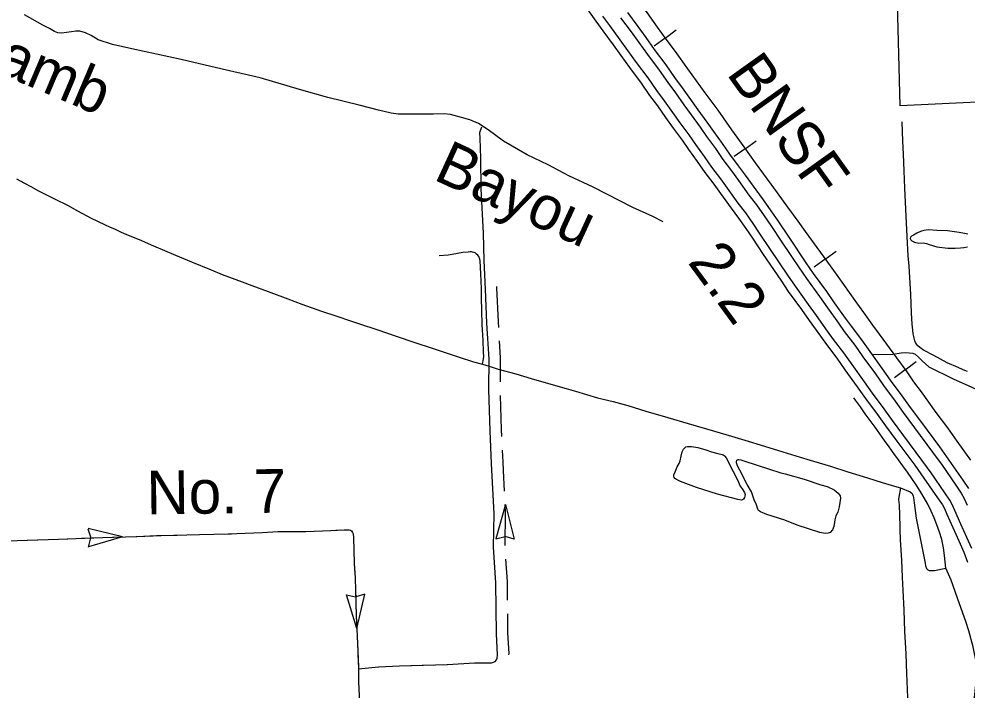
# Model space of a CAD drawing. Extents: x -117616 to 64730, y 54117 to 789866.
# Drawn here: x 62704.7 to 62888.1, y 54864.5 to 54994.3 of the extents above; entities that cross this region are included whole.
import ezdxf

# ---------------------------------------------------------------- set-up
doc = ezdxf.new("R2010")
doc.units = 0
for name, color, linetype in [('15', 7, 'Continuous'), ('27', 7, 'Continuous'), ('33', 7, 'Continuous'), ('34', 7, 'Continuous'), ('35', 7, 'Continuous'), ('40', 7, 'Continuous'), ('43', 7, 'Continuous'), ('48', 7, 'Continuous'), ('6', 7, 'Continuous')]:
    doc.layers.add(name, color=color, linetype=linetype)

msp = doc.modelspace()

# ---------------------------------------------------------------- linework, layer by layer
at = {"layer": '15'}
for points in [[(62814.33, 54996.58), (62816.27, 54993.87), (62817.59, 54992.01), (62819.63, 54989.27), (62821.11, 54987.23), (62822.76, 54984.88), (62825.02, 54981.9), (62826.68, 54979.48), (62828.18, 54977.48), (62829.77, 54975.21), (62831.22, 54973.21), (62832.94, 54970.87), (62834.21, 54969.05), (62835.89, 54966.73), (62837.36, 54964.61), (62839.07, 54962.35), (62840.36, 54960.55), (62842.45, 54957.68), (62843.88, 54955.8), (62845.28, 54953.78), (62846.55, 54951.92), (62848.67, 54948.76), (62852.03, 54943.77), (62853.51, 54941.61), (62856.06, 54938.11), (62857.57, 54935.96), (62859.71, 54932.95), (62860.88, 54931.32), (62862.87, 54928.69), (62864.45, 54926.46), (62866.85, 54923.16), (62868.43, 54920.91), (62870.68, 54917.87), (62872.28, 54915.64), (62874.49, 54912.66), (62877.96, 54907.99), (62879.75, 54905.52), (62882.38, 54901.69), (62883.32, 54900.33), (62883.7, 54899.65), (62884.19, 54898.53), (62885.35, 54895.93), (62886.49, 54893.35), (62887.46, 54891.21), (62888.2, 54889.23)], [(62888.43, 54903.49), (62887.32, 54905.09), (62884.66, 54908.98), (62882.8, 54911.54), (62879.31, 54916.23), (62877.13, 54919.17), (62875.53, 54921.41), (62873.3, 54924.42), (62871.73, 54926.65), (62869.32, 54929.96), (62867.72, 54932.23), (62865.71, 54934.88), (62864.59, 54936.44), (62862.47, 54939.42), (62860.94, 54941.6), (62858.41, 54945.08), (62856.99, 54947.14), (62853.65, 54952.11), (62851.52, 54955.28), (62850.22, 54957.18), (62848.73, 54959.33), (62847.26, 54961.26), (62845.23, 54964.06), (62843.9, 54965.91), (62842.22, 54968.13), (62840.78, 54970.2), (62839.1, 54972.53), (62837.82, 54974.36), (62836.07, 54976.75), (62834.66, 54978.69), (62833.04, 54981.01), (62831.56, 54982.98), (62829.89, 54985.41), (62827.61, 54988.42), (62825.99, 54990.72), (62824.46, 54992.82), (62822.44, 54995.54)], [(62889.03, 54891.86), (62888.05, 54894.05), (62886.91, 54896.62), (62885.75, 54899.22), (62885.22, 54900.41), (62884.77, 54901.22), (62883.78, 54902.65), (62881.14, 54906.5), (62879.33, 54909), (62875.85, 54913.67), (62873.66, 54916.64), (62872.05, 54918.88), (62869.81, 54921.91), (62868.23, 54924.15), (62865.83, 54927.45), (62864.25, 54929.7), (62862.25, 54932.33), (62861.09, 54933.94), (62858.96, 54936.94), (62857.44, 54939.1), (62854.9, 54942.6), (62853.43, 54944.72), (62850.08, 54949.71), (62847.96, 54952.87), (62846.68, 54954.75), (62845.26, 54956.8), (62843.81, 54958.69), (62841.74, 54961.55), (62840.44, 54963.36), (62838.74, 54965.61), (62837.27, 54967.72), (62835.59, 54970.04), (62834.32, 54971.86), (62832.59, 54974.21), (62831.15, 54976.2), (62829.56, 54978.48), (62828.06, 54980.47), (62826.4, 54982.9), (62824.14, 54985.88), (62822.49, 54988.22), (62821, 54990.27), (62818.97, 54993.01), (62817.65, 54994.86)], [(62821.07, 54994.54), (62823.09, 54991.81), (62824.61, 54989.73), (62826.24, 54987.42), (62828.51, 54984.42), (62830.18, 54981.98), (62831.66, 54980.01), (62833.27, 54977.71), (62834.69, 54975.75), (62836.44, 54973.37), (62837.71, 54971.54), (62839.4, 54969.22), (62840.84, 54967.13), (62842.53, 54964.9), (62843.85, 54963.07), (62845.9, 54960.25), (62847.36, 54958.33), (62848.82, 54956.22), (62850.11, 54954.33), (62852.24, 54951.16), (62855.58, 54946.19), (62857.02, 54944.1), (62859.56, 54940.61), (62861.08, 54938.44), (62863.21, 54935.45), (62864.34, 54933.87), (62866.35, 54931.23), (62867.94, 54928.97), (62870.35, 54925.66), (62871.92, 54923.43), (62874.15, 54920.41), (62875.76, 54918.17), (62877.94, 54915.22), (62881.43, 54910.54), (62883.27, 54908), (62885.92, 54904.13), (62886.98, 54902.59), (62887.55, 54901.56), (62888.12, 54900.28)]]:
    msp.add_lwpolyline(points, dxfattribs=at)
at = {"layer": '27'}
for points in [[(62883.96, 54888.07), (62883.74, 54890.52), (62883.51, 54892.03), (62883.19, 54893.65), (62882.73, 54895.06), (62882.24, 54896.45), (62881.71, 54897.81), (62881.12, 54899.14), (62880.47, 54900.45), (62879.77, 54901.72), (62879.03, 54902.98), (62878.24, 54904.22), (62877.41, 54905.44), (62876.54, 54906.64), (62875.68, 54907.85), (62874.8, 54909.07), (62873.92, 54910.29), (62873.03, 54911.53), (62872.12, 54912.79), (62871.2, 54914.06), (62870.28, 54915.34), (62869.34, 54916.63), (62868.4, 54917.94), (62867.46, 54919.26), (62866.5, 54920.58), (62866.18, 54921.03)], [(62890.36, 54854.84), (62889.64, 54857.65), (62889.48, 54859.72), (62889.37, 54861.95), (62889.58, 54863.65), (62889.79, 54865.56), (62890.01, 54867.58), (62890.01, 54869.38), (62889.26, 54872.89), (62888.41, 54875.97), (62887.88, 54877.78), (62886.61, 54881.17), (62885.02, 54885.74), (62883.96, 54888.07)]]:
    msp.add_lwpolyline(points, dxfattribs=at)
at = {"layer": '33'}
for points in [[(62704.16, 54963.36), (62705.73, 54962.54), (62706.98, 54961.89), (62708.44, 54961.07), (62711.65, 54959.45), (62714.02, 54958.27), (62716, 54957.22), (62718.65, 54955.79), (62721.2, 54954.55), (62722.28, 54954.05), (62723.17, 54953.69), (62724.45, 54953.05), (62725.76, 54952.5), (62727.9, 54951.63), (62730.67, 54950.45), (62734.96, 54948.64), (62738.06, 54947.33), (62741.86, 54945.79), (62743.99, 54944.91), (62747.87, 54943.47), (62749.74, 54942.73), (62752.89, 54941.56), (62756.7, 54940.16), (62759.4, 54939.14), (62763.18, 54937.82), (62766.16, 54936.81), (62768.83, 54935.9), (62770.36, 54935.38), (62774.09, 54934.17), (62777.65, 54932.95), (62781.25, 54931.72), (62784.39, 54930.72), (62789.83, 54928.87), (62792.59, 54928.01), (62794.31, 54927.55)], [(62794.31, 54927.55), (62795.64, 54927.16), (62797.39, 54926.59), (62800.81, 54925.64), (62803.76, 54924.77), (62808, 54923.56), (62810.51, 54922.84), (62812.34, 54922.31), (62816.62, 54921.06), (62819.59, 54920.3), (62822.43, 54919.52), (62825.96, 54918.48), (62830.17, 54917.24), (62834.14, 54916.06), (62839.22, 54914.57), (62842.49, 54913.6), (62845.11, 54912.86), (62848.89, 54911.66), (62852.43, 54910.61), (62854.98, 54909.82), (62858.35, 54908.81), (62861.69, 54907.81), (62865.05, 54906.69), (62868.85, 54905.57), (62871.66, 54904.67), (62874.05, 54903.96), (62875.2, 54903.6)], [(62875.2, 54903.6), (62877.09, 54902.85), (62877.47, 54902.51), (62877.68, 54902.04), (62877.71, 54901.73), (62877.88, 54900.74), (62878.26, 54897.77), (62879.96, 54889.07), (62880.06, 54888.52), (62880.23, 54888.04), (62880.47, 54887.74), (62880.75, 54887.63), (62881.8, 54887.63), (62883.96, 54888.07)]]:
    msp.add_lwpolyline(points, dxfattribs=at)
at = {"layer": '34'}
for points in [[(62888.15, 54926.1), (62887.36, 54926.43), (62886.35, 54926.89), (62884.26, 54927.81), (62881.66, 54929.19), (62879.67, 54930.26), (62878.94, 54930.74), (62878.59, 54931.06), (62878.29, 54931.4), (62878.11, 54931.72), (62877.96, 54932.06), (62877.89, 54932.32), (62877.85, 54932.58), (62877.79, 54932.92), (62877.69, 54933.39), (62877.58, 54934.14), (62877.5, 54935.25), (62877.35, 54937.45), (62877.18, 54941.01), (62876.87, 54946.46), (62876.7, 54948.5), (62876.48, 54952.21), (62876.32, 54956.19), (62876.07, 54961.59), (62875.92, 54964.9), (62875.77, 54968.17), (62875.68, 54970.65), (62875.52, 54974.38)], [(62794.31, 54927.55), (62794.54, 54928.57), (62794.58, 54929.05), (62794.56, 54929.85), (62794.45, 54932.18), (62794.3, 54935.13), (62794.21, 54937.95), (62794.14, 54940.26), (62794.13, 54942.2), (62793.99, 54945.03), (62793.88, 54947.51), (62793.8, 54947.83), (62793.61, 54948.37), (62793.42, 54948.59), (62793.15, 54948.84), (62792.89, 54949.05), (62792.7, 54949.13), (62792.39, 54949.21), (62792.19, 54949.24), (62791.96, 54949.25), (62791.57, 54949.22), (62790.53, 54949.11), (62788.5, 54948.73), (62787.73, 54948.64), (62785.98, 54948.5)], [(62875.2, 54903.6), (62874.89, 54901.8), (62874.85, 54901.39), (62874.88, 54900.84), (62874.93, 54900.32), (62874.98, 54899.84), (62875.01, 54898.88), (62875.11, 54895.58), (62875.18, 54893.54), (62875.39, 54889.61), (62875.55, 54886.35), (62875.68, 54883.76), (62875.83, 54880), (62875.97, 54875.86), (62876.13, 54873.71), (62876.17, 54872.63), (62876.22, 54871.49), (62876.37, 54867.69), (62876.62, 54861.55)]]:
    msp.add_lwpolyline(points, dxfattribs=at)
at = {"layer": '35'}
for points in [[(62829.28, 54955.08), (62827.3, 54956.08), (62823.43, 54957.86), (62815.76, 54961.76), (62811.06, 54963.98), (62807.03, 54966.08), (62803, 54968.02), (62798.39, 54970.66), (62795.43, 54972.86), (62793.56, 54974.11), (62791.88, 54974.76), (62790.27, 54975.21), (62788.14, 54975.82), (62786.92, 54975.98), (62784.85, 54975.86), (62780.79, 54975.89), (62778.05, 54975.86), (62776.67, 54976.05), (62774.25, 54976.69), (62770.51, 54977.63), (62764.42, 54979.08), (62758.94, 54980.66), (62751.3, 54982.89), (62743.98, 54984.57), (62736.02, 54986.47), (62726.48, 54988.53), (62722.74, 54989.37), (62720, 54990.27), (62718.62, 54991.11), (62717.52, 54991.63), (62716.43, 54991.95), (62715.69, 54991.92), (62714.82, 54991.82), (62712.91, 54991.57), (62712.17, 54991.63), (62711.56, 54991.89), (62710.59, 54992.44), (62709.3, 54993.11), (62705.73, 54995.11)], [(62888.26, 54952.65), (62887.58, 54952.82), (62886.54, 54952.99), (62884.31, 54953.33), (62882.22, 54953.39), (62880.62, 54953.53), (62879.74, 54953.41), (62879.07, 54953.19), (62878.39, 54952.85), (62877.72, 54952.51), (62877.35, 54952.29), (62877.15, 54952.09), (62877.07, 54951.86), (62877.18, 54951.58), (62877.38, 54951.41), (62877.94, 54951.1), (62878.79, 54950.93), (62879.6, 54950.99), (62880.22, 54950.88), (62880.76, 54950.65), (62882.22, 54950.23), (62884.34, 54949.97), (62885.8, 54950), (62886.79, 54950.06), (62887.44, 54950.09), (62888.2, 54950.2)], [(62869.67, 54929.49), (62870.94, 54929.43), (62873.76, 54929.5), (62875.32, 54929.75), (62876.15, 54929.78), (62877.61, 54929.69), (62878.02, 54929.5), (62878.69, 54928.92), (62879.39, 54928.16), (62880.72, 54927.02), (62885.42, 54924.73), (62889.01, 54923.11), (62893.71, 54920.88), (62901.43, 54917.54), (62903.97, 54916.75), (62906.51, 54915.99), (62909.82, 54915), (62911.91, 54914.52), (62913.72, 54914.46), (62917.66, 54914.55), (62927, 54914.59)], [(62841.46, 54909.41), (62842.78, 54906.89), (62843.67, 54905.17), (62844.21, 54903.97), (62844.58, 54903.45), (62845.02, 54902.74), (62845.13, 54902.32), (62845.1, 54901.99), (62845.02, 54901.75), (62844.84, 54901.44), (62844.66, 54901.28), (62844.45, 54901.26), (62843.72, 54901.39), (62839.83, 54902.43), (62835.74, 54903.71), (62832.64, 54904.83), (62831.86, 54905.25), (62831.52, 54905.45), (62831.42, 54905.61), (62831.39, 54905.85), (62831.34, 54906.11), (62831.6, 54906.71), (62832.02, 54907.7), (62832.36, 54908.35), (62832.59, 54908.87), (62832.8, 54909.78), (62832.95, 54910.57), (62833.24, 54911.09), (62833.71, 54911.56), (62834.02, 54911.64), (62834.78, 54911.64), (62836.03, 54911.45), (62837.54, 54910.96), (62838.64, 54910.57), (62839.89, 54910.28), (62840.68, 54910.08), (62840.89, 54910), (62841.08, 54909.89), (62841.22, 54909.75), (62841.46, 54909.41)], [(62852.88, 54906.32), (62856.55, 54905.31), (62859.78, 54904.2), (62861.03, 54903.85), (62862.41, 54903.22), (62863.13, 54902.6), (62863.53, 54902.07), (62863.58, 54901.62), (62863.34, 54899.97), (62863.08, 54898.91), (62862.68, 54898.22), (62862.49, 54897.42), (62862.47, 54897), (62862.31, 54896.17), (62862.04, 54895.48), (62861.62, 54895), (62861.25, 54894.85), (62860.61, 54894.79), (62859.63, 54894.98), (62857.42, 54895.72), (62855.22, 54896.39), (62852.83, 54897.4), (62849.32, 54898.49), (62848.13, 54898.99), (62847.73, 54899.23), (62847.62, 54899.47), (62847.36, 54900.35), (62846.88, 54901.3), (62846.38, 54902.87), (62845.55, 54904.28), (62844.92, 54905.47), (62844.39, 54906.56), (62843.85, 54907.47), (62843.62, 54908.1), (62843.46, 54908.48), (62843.46, 54908.72), (62843.56, 54908.98), (62843.78, 54909.09), (62843.91, 54909.11), (62844.33, 54909.06), (62845.1, 54908.8), (62849.67, 54907.31), (62852.06, 54906.51), (62852.88, 54906.32)]]:
    msp.add_lwpolyline(points, dxfattribs=at)
at = {"layer": '40'}
for p, q in [((62829.68, 54990.61), (62831.8, 54992.17)), ((62829.68, 54990.61), (62827.55, 54989.04)), ((62845.15, 54969.21), (62847.29, 54970.76)), ((62845.15, 54969.21), (62843.01, 54967.67)), ((62860.64, 54947.84), (62858.5, 54946.29)), ((62860.64, 54947.84), (62862.78, 54949.38)), ((62876.14, 54926.47), (62878.25, 54928.06)), ((62876.14, 54926.47), (62874.03, 54924.88))]:
    msp.add_line(p, q, dxfattribs=at)
msp.add_lwpolyline([(62825.36, 54996.63), (62828.13, 54992.71), (62829.83, 54990.4), (62831.61, 54987.98), (62834.03, 54984.65), (62837.33, 54980.04), (62839.86, 54976.63), (62842.52, 54972.88), (62844.88, 54969.58), (62847.12, 54966.49), (62849.41, 54963.3), (62851.35, 54960.69), (62853.37, 54957.87), (62855.34, 54955.18), (62856.77, 54953.18), (62857.97, 54951.53), (62860.74, 54947.7), (62863.08, 54944.5), (62866.35, 54939.82), (62868.08, 54937.5), (62869.81, 54935.08), (62871.11, 54933.32), (62874.41, 54928.77), (62876.43, 54926.08), (62877.73, 54924.14), (62879.2, 54922.19), (62882.07, 54918.17), (62884.28, 54915.22), (62886.09, 54912.64), (62888.75, 54908.96)], dxfattribs=at)
msp.add_lwpolyline([(62825.36, 54996.63), (62828.13, 54992.71), (62829.83, 54990.4), (62831.61, 54987.98), (62834.03, 54984.65), (62837.33, 54980.04), (62839.86, 54976.63), (62842.52, 54972.88), (62844.88, 54969.58), (62847.12, 54966.49), (62849.41, 54963.3), (62851.35, 54960.69), (62853.37, 54957.87), (62855.34, 54955.18), (62856.77, 54953.18), (62857.97, 54951.53), (62860.74, 54947.7), (62863.08, 54944.5), (62866.35, 54939.82), (62868.08, 54937.5), (62869.81, 54935.08), (62871.11, 54933.32), (62874.41, 54928.77), (62876.43, 54926.08), (62877.73, 54924.14), (62879.2, 54922.19), (62882.07, 54918.17), (62884.28, 54915.22), (62886.09, 54912.64), (62888.75, 54908.96)], dxfattribs=at)
at = {"layer": '43'}
for p, q in [((62798.8, 54900.37), (62796.94, 54893.77)), ((62798.8, 54900.37), (62800.49, 54893.72)), ((62718, 54895.71), (62718.54, 54893.97)), ((62724.7, 54894.16), (62718.02, 54895.74)), ((62724.7, 54894.16), (62718.12, 54892.19)), ((62718.14, 54892.16), (62718.54, 54893.94)), ((62796.94, 54893.77), (62798.71, 54894.22)), ((62800.49, 54893.72), (62798.73, 54894.22)), ((62770, 54876.39), (62768.01, 54882.96)), ((62768.01, 54882.96), (62769.79, 54882.55)), ((62771.56, 54883.08), (62769.81, 54882.55)), ((62770, 54876.39), (62771.56, 54883.08))]:
    msp.add_line(p, q, dxfattribs=at)
for points in [[(62770.35, 54868.65), (62774.23, 54869.02), (62778.3, 54869.18), (62787.6, 54869.47), (62792.82, 54869.8), (62794.96, 54869.8), (62796.11, 54869.8), (62796.44, 54869.88), (62796.77, 54870.01), (62797.06, 54870.38), (62797.18, 54870.71), (62797.26, 54871.32), (62797.06, 54875.36), (62796.94, 54885.24), (62796.48, 54892.15), (62796.57, 54898.58), (62796.11, 54908.33), (62795.82, 54914.67), (62795.58, 54922.66), (62795.62, 54928.5), (62795.21, 54935.46), (62794.92, 54942.05), (62794.67, 54947.61), (62794.55, 54952.87), (62794.1, 54961.44), (62794.02, 54967.37), (62793.89, 54971.24), (62793.85, 54972.35), (62794.22, 54973.42)], [(62797.48, 54934.66), (62797.42, 54935.71), (62797.13, 54942.29), (62797.12, 54942.57)], [(62797.8, 54924.11), (62797.83, 54928.75), (62797.64, 54932.03)], [(62798.1, 54913.56), (62798.04, 54914.92), (62797.84, 54921.47)], [(62798.4, 54906.97), (62798.33, 54908.58), (62798.22, 54910.92)], [(62798.59, 54903.01), (62798.4, 54906.97)], [(62798.7, 54892.45), (62798.78, 54898.82), (62798.71, 54900.37)], [(62702.33, 54893.36), (62712.32, 54893.71), (62720.84, 54894.04), (62727.46, 54894.23), (62732.19, 54894.42), (62739.59, 54894.59), (62745.14, 54894.71), (62751.79, 54894.97), (62754.73, 54895.18), (62756.27, 54895.16), (62760.14, 54895.21), (62765.01, 54895.37), (62767.59, 54895.52), (62768.52, 54895.47), (62768.78, 54895.42), (62768.97, 54895.28), (62769.18, 54894.99), (62769.33, 54894.71), (62769.37, 54894.02), (62769.54, 54889.06), (62769.68, 54886.23), (62769.92, 54878.89), (62770.08, 54874.97), (62770.35, 54868.99), (62770.37, 54866.09), (62770.8, 54856.61)], [(62737.89, 54894.55), (62739.59, 54894.59), (62745.14, 54894.71), (62745.81, 54894.74)], [(62748.44, 54894.84), (62751.79, 54894.97), (62754.73, 54895.18), (62756.27, 54895.16), (62756.35, 54895.16)], [(62758.99, 54895.19), (62760.14, 54895.21), (62765.01, 54895.37), (62766.91, 54895.48)], [(62769.26, 54894.84), (62769.33, 54894.71), (62769.37, 54894.02), (62769.54, 54889.06), (62769.64, 54886.95)], [(62706.23, 54893.49), (62712.32, 54893.71), (62714.14, 54893.78)], [(62716.78, 54893.89), (62720.84, 54894.04), (62724.7, 54894.16)], [(62727.33, 54894.23), (62727.46, 54894.23), (62731.29, 54894.39)], [(62731.29, 54894.39), (62732.19, 54894.42), (62735.25, 54894.49)], [(62799.19, 54881.91), (62799.15, 54885.48), (62798.87, 54889.82)], [(62769.74, 54884.31), (62769.92, 54878.89), (62770.02, 54876.39)], [(62799.45, 54871.36), (62799.48, 54871.57), (62799.27, 54875.6), (62799.23, 54879.27)], [(62770.14, 54873.76), (62770.31, 54869.8)], [(62770.31, 54869.8), (62770.35, 54868.99), (62770.37, 54866.09), (62770.38, 54865.84)], [(62770.35, 54868.65), (62774.23, 54869.02), (62774.29, 54869.02)], [(62776.93, 54869.13), (62778.3, 54869.18), (62784.84, 54869.39)], [(62787.48, 54869.47), (62787.6, 54869.47), (62792.82, 54869.8), (62794.96, 54869.8), (62795.39, 54869.8)]]:
    msp.add_lwpolyline(points, dxfattribs=at)
at = {"layer": '6'}
msp.add_lwpolyline([(62903.4, 54951.68), (62902.28, 54978.76), (62875.14, 54977.48), (62873.99, 55022.17), (62872.34, 55055.76)], dxfattribs=at)

# ---------------------------------------------------------------- texts
at = {"layer": '35'}
for s, rotation, p in [('Lamb', 337.0056, (62694.14, 54986.57)), ('Bayou', 335.3008, (62784.62, 54963.34))]:
    msp.add_text(s, height=8.448, rotation=rotation, dxfattribs=at).set_placement(p)
at = {"layer": '40'}
msp.add_text('BNSF', height=8.448, rotation=305.5098, dxfattribs=at).set_placement((62841.4, 54983.75))
at = {"layer": '43'}
msp.add_text('No. 7', height=8.448, rotation=0.7855, dxfattribs=at).set_placement((62729.39, 54898.47))
at = {"layer": '48'}
msp.add_text('2.2', height=8.448, rotation=306.3305, dxfattribs=at).set_placement((62833.9, 54947.27))

doc.saveas('drawing.dxf')
